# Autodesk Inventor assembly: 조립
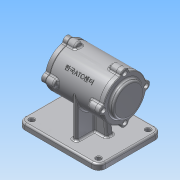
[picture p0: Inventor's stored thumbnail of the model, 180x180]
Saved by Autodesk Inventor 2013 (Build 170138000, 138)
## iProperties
Created: 2015-12
Part Number: 조립
Document SubType Name: Assembly
Designer: Administrator
Author: Administrator
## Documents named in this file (5)
- C:\Users\Administrator\Desktop\451208V1033\조립.iam
- C:\Users\Administrator\Desktop\451208V1033\본체.ipt
- C:\Users\Administrator\Desktop\451208V1033\커버.ipt
- C:\Users\Administrator\Desktop\451208V1033\커버2.ipt
- C:\Users\Administrator\Desktop\451208V1033\베어링 6204.ipt
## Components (2 placed, 1 different names)
1. KS B 2023 6204 - 20 x 47 x 14:1
2. KS B 2023 6204 - 20 x 47 x 14:2
